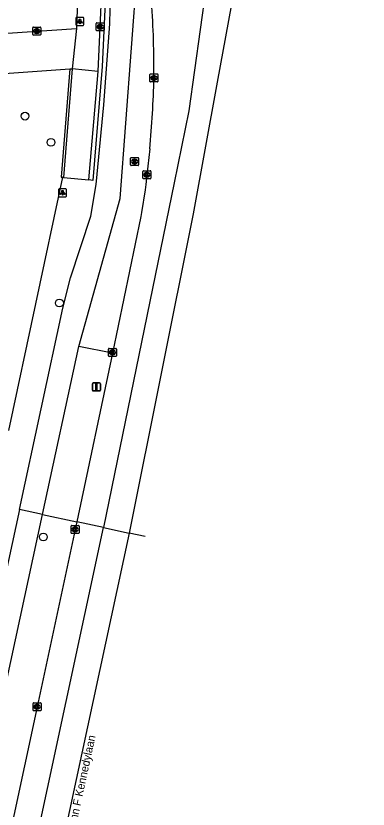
# Model space of a CAD drawing. Extents: x 161253 to 161848, y 384872 to 385383.
# Drawn here: x 161799 to 161843, y 385099.3 to 385198.5 of the extents above; entities that cross this region are included whole.
import ezdxf

# ---------------------------------------------------------------- set-up
doc = ezdxf.new("R2010")
doc.units = 0
for name, color, linetype in [('IMGEO_Berm_groen', 7, 'Continuous'), ('IMGEO_Berm_open', 7, 'Continuous'), ('IMGEO_Boom', 7, 'Continuous'), ('IMGEO_Fietspad_open', 7, 'Continuous'), ('IMGEO_Kolk', 7, 'Continuous'), ('IMGEO_Lichtpunt', 7, 'Continuous'), ('IMGEO_Muur', 7, 'Continuous'), ('IMGEO_Openbare_ruimte_label', 7, 'Continuous'), ('IMGEO_Parkeervlak_open', 7, 'Continuous'), ('IMGEO_Rijbaan_lokaal_open', 7, 'Continuous'), ('IMGEO_Rijbaan_regionaal_gesloten', 7, 'Continuous'), ('IMGEO_Rioolput', 7, 'Continuous'), ('IMGEO_Verkeersbordpaal', 7, 'Continuous'), ('IMGEO_Voetpad_gesloten', 7, 'Continuous'), ('IMGEO_Voetpad_open', 7, 'Continuous')]:
    doc.layers.add(name, color=color, linetype=linetype)

msp = doc.modelspace()

# ---------------------------------------------------------------- linework, layer by layer
at = {"layer": 'IMGEO_Berm_groen'}
msp.add_lwpolyline([(161802.317, 385136.129), (161806.58, 385135.222)], dxfattribs=at)
at = {"layer": 'IMGEO_Berm_open'}
msp.add_lwpolyline([(161811.067, 385156.299), (161806.85, 385157.128)], dxfattribs=at)
at = {"layer": 'IMGEO_Boom'}
for centre in [(161800.125, 385185.921), (161803.37, 385182.642), (161804.424, 385162.564), (161802.419, 385133.327)]:
    msp.add_circle(centre, 0.489, dxfattribs=at)
at = {"layer": 'IMGEO_Fietspad_open'}
for points in [[(161799.416, 385136.747), (161804.851, 385161.932), (161805.798, 385165.717), (161808.364, 385173.407), (161809.023, 385177.396), (161809.973, 385187.32), (161810.725, 385197.446), (161810.795, 385201.149), (161811.014, 385207.171), (161808.054, 385250), (161801.247, 385347.561), (161799.482, 385356.188)], [(161806.85, 385157.128), (161812.029, 385175.625), (161814.159, 385203.908), (161813.652, 385212.427), (161806.814, 385309.979), (161806.751, 385311.045)], [(161802.317, 385136.129), (161806.85, 385157.128)], [(161802.317, 385136.129), (161799.416, 385136.747)]]:
    msp.add_lwpolyline(points, dxfattribs=at)
at = {"layer": 'IMGEO_Kolk'}
for p, q in [((161809.027, 385196.66), (161809.027, 385197.512)), ((161809.102, 385197.586), (161809.954, 385197.586)), ((161809.515, 385197.366), (161809.54, 385197.366)), ((161810.028, 385197.512), (161810.028, 385196.66)), ((161801.097, 385196.119), (161801.097, 385196.971)), ((161801.172, 385197.045), (161802.024, 385197.045)), ((161801.608, 385196.265), (161801.583, 385196.265)), ((161801.585, 385196.825), (161801.61, 385196.825)), ((161802.098, 385196.971), (161802.098, 385196.119)), ((161809.954, 385196.586), (161809.102, 385196.586)), ((161809.538, 385196.806), (161809.513, 385196.806)), ((161802.024, 385196.045), (161801.172, 385196.045)), ((161815.733, 385190.266), (161815.733, 385191.118)), ((161815.808, 385191.192), (161816.66, 385191.192)), ((161816.244, 385190.412), (161816.219, 385190.412)), ((161816.221, 385190.972), (161816.246, 385190.972)), ((161816.734, 385191.118), (161816.734, 385190.266)), ((161816.66, 385190.192), (161815.808, 385190.192)), ((161814.852, 385178.165), (161814.852, 385179.017)), ((161814.927, 385179.091), (161815.779, 385179.091)), ((161815.363, 385178.311), (161815.338, 385178.311)), ((161815.34, 385178.871), (161815.365, 385178.871)), ((161815.853, 385179.017), (161815.853, 385178.165)), ((161815.779, 385178.091), (161814.927, 385178.091)), ((161810.545, 385155.966), (161810.545, 385156.818)), ((161810.62, 385156.892), (161811.472, 385156.892)), ((161811.033, 385156.672), (161811.058, 385156.672)), ((161811.546, 385156.818), (161811.546, 385155.966)), ((161811.472, 385155.892), (161810.62, 385155.892)), ((161811.056, 385156.112), (161811.031, 385156.112)), ((161805.874, 385133.838), (161805.874, 385134.69)), ((161805.949, 385134.764), (161806.801, 385134.764)), ((161806.875, 385134.69), (161806.875, 385133.838)), ((161806.801, 385133.764), (161805.949, 385133.764)), ((161806.385, 385133.984), (161806.36, 385133.984)), ((161806.362, 385134.544), (161806.387, 385134.544)), ((161801.123, 385111.681), (161801.123, 385112.533)), ((161801.198, 385112.607), (161802.05, 385112.607)), ((161801.611, 385112.387), (161801.636, 385112.387)), ((161802.124, 385112.533), (161802.124, 385111.681)), ((161802.05, 385111.607), (161801.198, 385111.607)), ((161801.634, 385111.827), (161801.609, 385111.827))]:
    msp.add_line(p, q, dxfattribs=at)
for points in [[(161809.027, 385196.66), (161809.027, 385197.512)], [(161809.102, 385197.586), (161809.954, 385197.586)], [(161809.348, 385197.286), (161809.471, 385197.286), (161809.471, 385197.135), (161809.601, 385197.286), (161809.765, 385197.286), (161809.619, 385197.135), (161809.772, 385196.886), (161809.62, 385196.886), (161809.535, 385197.05), (161809.471, 385196.983), (161809.471, 385196.886), (161809.348, 385196.886), (161809.348, 385197.286)], [(161810.028, 385197.512), (161810.028, 385196.66)], [(161801.097, 385196.119), (161801.097, 385196.971)], [(161801.172, 385197.045), (161802.024, 385197.045)], [(161801.418, 385196.745), (161801.541, 385196.745), (161801.541, 385196.594), (161801.671, 385196.745), (161801.835, 385196.745), (161801.689, 385196.594), (161801.842, 385196.345), (161801.69, 385196.345), (161801.605, 385196.509), (161801.541, 385196.442), (161801.541, 385196.345), (161801.418, 385196.345), (161801.418, 385196.745)], [(161802.098, 385196.971), (161802.098, 385196.119)], [(161809.954, 385196.586), (161809.102, 385196.586)], [(161802.024, 385196.045), (161801.172, 385196.045)], [(161815.733, 385190.266), (161815.733, 385191.118)], [(161815.808, 385191.192), (161816.66, 385191.192)], [(161816.054, 385190.892), (161816.177, 385190.892), (161816.177, 385190.741), (161816.307, 385190.892), (161816.471, 385190.892), (161816.325, 385190.741), (161816.478, 385190.492), (161816.326, 385190.492), (161816.241, 385190.656), (161816.177, 385190.589), (161816.177, 385190.492), (161816.054, 385190.492), (161816.054, 385190.892)], [(161816.734, 385191.118), (161816.734, 385190.266)], [(161816.66, 385190.192), (161815.808, 385190.192)], [(161814.852, 385178.165), (161814.852, 385179.017)], [(161814.927, 385179.091), (161815.779, 385179.091)], [(161815.173, 385178.791), (161815.296, 385178.791), (161815.296, 385178.64), (161815.426, 385178.791), (161815.59, 385178.791), (161815.444, 385178.64), (161815.597, 385178.391), (161815.445, 385178.391), (161815.36, 385178.555), (161815.296, 385178.488), (161815.296, 385178.391), (161815.173, 385178.391), (161815.173, 385178.791)], [(161815.853, 385179.017), (161815.853, 385178.165)], [(161815.779, 385178.091), (161814.927, 385178.091)], [(161810.545, 385155.966), (161810.545, 385156.818)], [(161810.62, 385156.892), (161811.472, 385156.892)], [(161810.866, 385156.592), (161810.989, 385156.592), (161810.989, 385156.441), (161811.119, 385156.592), (161811.283, 385156.592), (161811.137, 385156.441), (161811.29, 385156.192), (161811.138, 385156.192), (161811.053, 385156.356), (161810.989, 385156.289), (161810.989, 385156.192), (161810.866, 385156.192), (161810.866, 385156.592)], [(161811.546, 385156.818), (161811.546, 385155.966)], [(161811.472, 385155.892), (161810.62, 385155.892)], [(161805.874, 385133.838), (161805.874, 385134.69)], [(161805.949, 385134.764), (161806.801, 385134.764)], [(161806.875, 385134.69), (161806.875, 385133.838)], [(161806.801, 385133.764), (161805.949, 385133.764)], [(161806.195, 385134.464), (161806.318, 385134.464), (161806.318, 385134.313), (161806.448, 385134.464), (161806.612, 385134.464), (161806.466, 385134.313), (161806.619, 385134.064), (161806.467, 385134.064), (161806.382, 385134.228), (161806.318, 385134.161), (161806.318, 385134.064), (161806.195, 385134.064), (161806.195, 385134.464)], [(161801.123, 385111.681), (161801.123, 385112.533)], [(161801.198, 385112.607), (161802.05, 385112.607)], [(161801.444, 385112.307), (161801.567, 385112.307), (161801.567, 385112.156), (161801.697, 385112.307), (161801.861, 385112.307), (161801.715, 385112.156), (161801.868, 385111.907), (161801.716, 385111.907), (161801.631, 385112.071), (161801.567, 385112.004), (161801.567, 385111.907), (161801.444, 385111.907), (161801.444, 385112.307)], [(161802.124, 385112.533), (161802.124, 385111.681)], [(161802.05, 385111.607), (161801.198, 385111.607)]]:
    msp.add_lwpolyline(points, dxfattribs=at)
for centre, start, end in [((161809.104, 385197.51), 91.55205, 178.44795), ((161809.104, 385197.51), 91.55205, 178.44795), ((161809.952, 385197.51), 1.55205, 88.44795), ((161809.952, 385197.51), 1.55205, 88.44795), ((161801.174, 385196.969), 91.55205, 178.44795), ((161801.174, 385196.969), 91.55205, 178.44795), ((161802.022, 385196.969), 1.55205, 88.44795), ((161802.022, 385196.969), 1.55205, 88.44795), ((161809.104, 385196.662), 181.55205, 268.44795), ((161809.104, 385196.662), 181.55205, 268.44795), ((161809.952, 385196.662), 271.55205, 358.44795), ((161809.952, 385196.662), 271.55205, 358.44795), ((161801.174, 385196.121), 181.55205, 268.44795), ((161801.174, 385196.121), 181.55205, 268.44795), ((161802.022, 385196.121), 271.55205, 358.44795), ((161802.022, 385196.121), 271.55205, 358.44795), ((161815.81, 385191.116), 91.55205, 178.44795), ((161815.81, 385191.116), 91.55205, 178.44795), ((161815.81, 385190.268), 181.55205, 268.44795), ((161815.81, 385190.268), 181.55205, 268.44795), ((161816.658, 385191.116), 1.55205, 88.44795), ((161816.658, 385191.116), 1.55205, 88.44795), ((161816.658, 385190.268), 271.55205, 358.44795), ((161816.658, 385190.268), 271.55205, 358.44795), ((161814.929, 385179.015), 91.55205, 178.44795), ((161814.929, 385179.015), 91.55205, 178.44795), ((161815.777, 385179.015), 1.55205, 88.44795), ((161815.777, 385179.015), 1.55205, 88.44795), ((161814.929, 385178.167), 181.55205, 268.44795), ((161814.929, 385178.167), 181.55205, 268.44795), ((161815.777, 385178.167), 271.55205, 358.44795), ((161815.777, 385178.167), 271.55205, 358.44795), ((161810.622, 385156.816), 91.55205, 178.44795), ((161810.622, 385156.816), 91.55205, 178.44795), ((161811.47, 385156.816), 1.55205, 88.44795), ((161811.47, 385156.816), 1.55205, 88.44795), ((161810.622, 385155.968), 181.55205, 268.44795), ((161810.622, 385155.968), 181.55205, 268.44795), ((161811.47, 385155.968), 271.55205, 358.44795), ((161811.47, 385155.968), 271.55205, 358.44795), ((161805.951, 385134.688), 91.55205, 178.44795), ((161805.951, 385134.688), 91.55205, 178.44795), ((161806.799, 385134.688), 1.55205, 88.44795), ((161806.799, 385134.688), 1.55205, 88.44795), ((161805.951, 385133.84), 181.55205, 268.44795), ((161805.951, 385133.84), 181.55205, 268.44795), ((161806.799, 385133.84), 271.55205, 358.44795), ((161806.799, 385133.84), 271.55205, 358.44795), ((161801.2, 385112.531), 91.55205, 178.44795), ((161801.2, 385112.531), 91.55205, 178.44795), ((161802.048, 385112.531), 1.55205, 88.44795), ((161802.048, 385112.531), 1.55205, 88.44795), ((161801.2, 385111.683), 181.55205, 268.44795), ((161801.2, 385111.683), 181.55205, 268.44795), ((161802.048, 385111.683), 271.55205, 358.44795), ((161802.048, 385111.683), 271.55205, 358.44795)]:
    msp.add_arc(centre, 0.0765, start, end, dxfattribs=at)
for centre, major_axis, ratio, start_param, end_param in [((161809.514, 385197.086), (-0.387, 0.002), 0.722429, 4.712389, 7.853982), ((161809.539, 385197.086), (-0.39, 0.002), 0.717154, 1.570796, 4.712389), ((161801.584, 385196.545), (-0.387, 0.002), 0.722429, 4.712389, 7.853982), ((161801.609, 385196.545), (-0.39, 0.002), 0.717154, 1.570796, 4.712389), ((161816.22, 385190.692), (-0.387, 0.002), 0.722429, 4.712389, 7.853982), ((161816.245, 385190.692), (-0.39, 0.002), 0.717154, 1.570796, 4.712389), ((161815.339, 385178.591), (-0.387, 0.002), 0.722429, 4.712389, 7.853982), ((161815.364, 385178.591), (-0.39, 0.002), 0.717154, 1.570796, 4.712389), ((161811.032, 385156.392), (-0.387, 0.002), 0.722429, 4.712389, 7.853982), ((161811.057, 385156.392), (-0.39, 0.002), 0.717154, 1.570796, 4.712389), ((161806.361, 385134.264), (-0.387, 0.002), 0.722429, 4.712389, 7.853982), ((161806.386, 385134.264), (-0.39, 0.002), 0.717154, 1.570796, 4.712389), ((161801.61, 385112.107), (-0.387, 0.002), 0.722429, 4.712389, 7.853982), ((161801.635, 385112.107), (-0.39, 0.002), 0.717154, 1.570796, 4.712389)]:
    msp.add_ellipse(centre, major_axis=major_axis, ratio=ratio, start_param=start_param, end_param=end_param, dxfattribs=at)
at = {"layer": 'IMGEO_Lichtpunt'}
for p, q in [((161806.48, 385198.162), (161806.48, 385197.355)), ((161806.48, 385198.162), (161806.48, 385197.355)), ((161807.382, 385198.257), (161806.574, 385198.257)), ((161807.382, 385198.257), (161806.574, 385198.257)), ((161807.476, 385197.355), (161807.476, 385198.162)), ((161807.476, 385197.355), (161807.476, 385198.162)), ((161806.574, 385197.261), (161807.382, 385197.261)), ((161806.574, 385197.261), (161807.382, 385197.261)), ((161804.312, 385176.743), (161804.312, 385175.936)), ((161804.312, 385176.743), (161804.312, 385175.936)), ((161805.214, 385176.838), (161804.406, 385176.838)), ((161805.214, 385176.838), (161804.406, 385176.838)), ((161805.308, 385175.936), (161805.308, 385176.743)), ((161805.308, 385175.936), (161805.308, 385176.743)), ((161804.406, 385175.842), (161805.214, 385175.842)), ((161804.406, 385175.842), (161805.214, 385175.842))]:
    msp.add_line(p, q, dxfattribs=at)
for points in [[(161806.854, 385197.826), (161806.893, 385197.798), (161806.705, 385197.536), (161806.667, 385197.563), (161806.854, 385197.826)], [(161806.956, 385197.778), (161807.003, 385197.778), (161807.003, 385197.456), (161806.956, 385197.456), (161806.956, 385197.778)], [(161807.066, 385197.798), (161807.104, 385197.825), (161807.291, 385197.563), (161807.252, 385197.535), (161807.066, 385197.798)], [(161804.686, 385176.407), (161804.725, 385176.379), (161804.537, 385176.117), (161804.499, 385176.144), (161804.686, 385176.407)], [(161804.788, 385176.359), (161804.835, 385176.359), (161804.835, 385176.037), (161804.788, 385176.037), (161804.788, 385176.359)], [(161804.898, 385176.379), (161804.936, 385176.406), (161805.123, 385176.144), (161805.084, 385176.116), (161804.898, 385176.379)]]:
    msp.add_lwpolyline(points, dxfattribs=at)
for centre in [(161806.979, 385197.96), (161804.811, 385176.541)]:
    msp.add_circle(centre, 0.0994, dxfattribs=at)
for centre, start, end in [((161806.574, 385198.162), 90, 180), ((161806.574, 385198.162), 90, 180), ((161807.382, 385198.162), 0, 90), ((161807.382, 385198.162), 0, 90), ((161806.574, 385197.355), 180, 270), ((161806.574, 385197.355), 180, 270), ((161807.382, 385197.355), 270, 0), ((161807.382, 385197.355), 270, 360), ((161804.406, 385176.743), 90, 180), ((161804.406, 385176.743), 90, 180), ((161805.214, 385176.743), 0, 90), ((161805.214, 385176.743), 0, 90), ((161804.406, 385175.936), 180, 270), ((161804.406, 385175.936), 180, 270), ((161805.214, 385175.936), 270, 0), ((161805.214, 385175.936), 270, 360)]:
    msp.add_arc(centre, 0.0946, start, end, dxfattribs=at)
at = {"layer": 'IMGEO_Muur'}
for points in [[(161809.266, 385191.488), (161809.957, 385207.224), (161806.977, 385250), (161800.175, 385347.621), (161800.798, 385347.634), (161807.52, 385250), (161810.465, 385207.275), (161809.778, 385192.126), (161808.589, 385177.868), (161808.119, 385177.946)], [(161808.119, 385177.946), (161809.266, 385191.488)]]:
    msp.add_lwpolyline(points, dxfattribs=at)
at = {"layer": 'IMGEO_Parkeervlak_open'}
msp.add_lwpolyline([(161781.243, 385190.099), (161805.722, 385191.83)], dxfattribs=at)
at = {"layer": 'IMGEO_Rijbaan_lokaal_open'}
for points in [[(161806.835, 385202.034), (161806.647, 385199.228), (161806.537, 385196.879)], [(161780.02, 385195.096), (161806.537, 385196.879)]]:
    msp.add_lwpolyline(points, dxfattribs=at)
at = {"layer": 'IMGEO_Rijbaan_regionaal_gesloten'}
for points in [[(161843.005, 385383.208), (161841.331, 385358.305), (161840.149, 385339.983), (161835.302, 385275.534), (161832.26, 385245.433), (161832.129, 385244.136), (161827.354, 385207.649), (161824.158, 385190.185), (161821.142, 385173.699), (161813.159, 385133.822)], [(161822.732, 385201.882), (161820.587, 385186.576), (161818.751, 385177.591), (161809.946, 385134.506)], [(161815.704, 385181.821), (161815.355, 385178.591), (161815.233, 385177.375), (161815.159, 385176.71), (161814.701, 385173.881), (161814.649, 385173.627), (161814.594, 385173.374), (161811.067, 385156.299)], [(161811.067, 385156.299), (161806.58, 385135.222)], [(161806.58, 385135.222), (161806.376, 385134.264), (161801.625, 385112.107), (161796.87, 385089.981), (161792.134, 385067.868), (161787.356, 385045.723), (161782.576, 385023.589), (161777.426, 385000), (161776.68, 384996.585), (161772.545, 384977.466), (161770.095, 384966.436)], [(161809.946, 385134.506), (161806.58, 385135.222)], [(161758.394, 384899.613), (161764.784, 384924.774), (161773.316, 384964.489), (161793.704, 385059.008), (161809.946, 385134.506)], [(161813.159, 385133.822), (161804.978, 385095.848), (161790.373, 385027.906), (161771.447, 384942.057), (161761.782, 384896.757), (161760.251, 384889.579), (161759.762, 384887.286)], [(161809.946, 385134.506), (161813.159, 385133.822)], [(161815.133, 385133.402), (161813.159, 385133.822)]]:
    msp.add_lwpolyline(points, dxfattribs=at)
for centre, radius, start, end in [((161695.35, 385191.661), 120.89, 359.54063, 4.03655), ((161688.246, 385193.916), 128.031, 354.57912, 358.55696)]:
    msp.add_arc(centre, radius, start, end, dxfattribs=at)
at = {"layer": 'IMGEO_Rioolput'}
for p, q in [((161813.319, 385179.824), (161813.319, 385180.676)), ((161813.394, 385180.75), (161814.246, 385180.75)), ((161813.807, 385180.53), (161813.832, 385180.53)), ((161814.32, 385180.676), (161814.32, 385179.824)), ((161814.246, 385179.75), (161813.394, 385179.75)), ((161813.83, 385179.97), (161813.805, 385179.97))]:
    msp.add_line(p, q, dxfattribs=at)
for points in [[(161813.319, 385179.824), (161813.319, 385180.676)], [(161813.394, 385180.75), (161814.246, 385180.75)], [(161813.908, 385180.448), (161813.656, 385180.45), (161813.656, 385180.05)], [(161813.834, 385180.369), (161813.78, 385180.369), (161813.78, 385180.288)], [(161814.32, 385180.676), (161814.32, 385179.824)], [(161814.246, 385179.75), (161813.394, 385179.75)], [(161813.656, 385180.05), (161813.78, 385180.05), (161813.78, 385180.212), (161813.791, 385180.212)], [(161813.78, 385180.288), (161813.832, 385180.288)], [(161813.838, 385180.183), (161813.909, 385180.05), (161814.049, 385180.05), (161813.984, 385180.176)]]:
    msp.add_lwpolyline(points, dxfattribs=at)
for centre, radius, start, end in [((161813.396, 385180.674), 0.0765, 91.55205, 178.44795), ((161813.396, 385180.674), 0.0765, 91.55205, 178.44795), ((161813.816, 385180.477), 0.19, 274.7715, 282.96867), ((161813.84, 385180.273), 0.0964, 77.00612, 93.18647), ((161813.854, 385180.33), 0.0378, 276.66336, 79.67722), ((161813.907, 385180.338), 0.109, 350.36119, 89.41601), ((161813.905, 385180.338), 0.112, 277.58423, 350.98172), ((161814.244, 385180.674), 0.0765, 1.55205, 88.44795), ((161814.244, 385180.674), 0.0765, 1.55205, 88.44795), ((161813.396, 385179.826), 0.0765, 181.55205, 268.44795), ((161813.396, 385179.826), 0.0765, 181.55205, 268.44795), ((161813.79, 385180.159), 0.0533, 26.02933, 88.69889), ((161813.889, 385180.123), 0.108, 29.51342, 73.79051), ((161814.244, 385179.826), 0.0765, 271.55205, 358.44795), ((161814.244, 385179.826), 0.0765, 271.55205, 358.44795)]:
    msp.add_arc(centre, radius, start, end, dxfattribs=at)
for centre, major_axis, ratio, start_param, end_param in [((161813.806, 385180.25), (-0.387, 0.002), 0.722429, 4.712389, 7.853982), ((161813.831, 385180.25), (-0.39, 0.002), 0.717154, 1.570796, 4.712389)]:
    msp.add_ellipse(centre, major_axis=major_axis, ratio=ratio, start_param=start_param, end_param=end_param, dxfattribs=at)
at = {"layer": 'IMGEO_Verkeersbordpaal'}
for p, q in [((161808.647, 385152.576), (161809.437, 385152.576)), ((161809.437, 385152.576), (161808.647, 385152.576)), ((161808.547, 385151.676), (161808.547, 385152.476)), ((161808.547, 385152.476), (161808.547, 385151.676)), ((161809.437, 385151.576), (161808.647, 385151.576)), ((161808.647, 385151.576), (161809.437, 385151.576)), ((161809.537, 385152.476), (161809.537, 385151.676)), ((161809.537, 385151.676), (161809.537, 385152.476))]:
    msp.add_line(p, q, dxfattribs=at)
msp.add_lwpolyline([(161808.967, 385152.451), (161809.117, 385152.451), (161809.117, 385151.701), (161808.967, 385151.701), (161808.967, 385152.451)], dxfattribs=at)
for centre, start, end in [((161808.647, 385152.476), 90, 180), ((161808.647, 385152.476), 90, 180), ((161809.437, 385152.476), 0, 90), ((161809.437, 385152.476), 360, 90), ((161808.647, 385151.676), 180, 270), ((161808.647, 385151.676), 180, 270), ((161809.437, 385151.676), 270, 0), ((161809.437, 385151.676), 270, 0)]:
    msp.add_arc(centre, 0.1, start, end, dxfattribs=at)
at = {"layer": 'IMGEO_Voetpad_gesloten'}
for points in [[(161799.416, 385136.747), (161769.904, 385000), (161768.985, 384995.754), (161766.76, 384985.38)], [(161762.945, 384953.53), (161765.884, 384967.112), (161767.508, 384974.642), (161771.563, 384993.626), (161772.932, 385000), (161802.317, 385136.129)]]:
    msp.add_lwpolyline(points, dxfattribs=at)
at = {"layer": 'IMGEO_Voetpad_open'}
for points in [[(161806.537, 385196.879), (161806.016, 385191.851)], [(161805.722, 385191.83), (161804.648, 385178.302), (161804.818, 385178.285)], [(161806.016, 385191.851), (161804.938, 385178.273)], [(161805.722, 385191.83), (161806.016, 385191.851)], [(161809.266, 385191.488), (161806.016, 385191.851)], [(161804.818, 385178.285), (161798.074, 385146.636)], [(161804.938, 385178.273), (161804.818, 385178.285)], [(161804.938, 385178.273), (161808.119, 385177.946)]]:
    msp.add_lwpolyline(points, dxfattribs=at)

# ---------------------------------------------------------------- texts
at = {"layer": 'IMGEO_Openbare_ruimte_label'}
msp.add_text('John F Kennedylaan', height=1, rotation=77.75714, dxfattribs=at).set_placement((161806.35, 385096.46))

doc.saveas('drawing.dxf')
